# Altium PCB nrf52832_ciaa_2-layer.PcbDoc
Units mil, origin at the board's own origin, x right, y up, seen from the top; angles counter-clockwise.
Board outline 354 x 353 mil, 4 copper layers (Top Layer, Mid-Layer 1, Mid-Layer 2, Bottom Layer), stack 39.8 mil thick; 14 components, 27 nets, 89 pads, 13 vias.
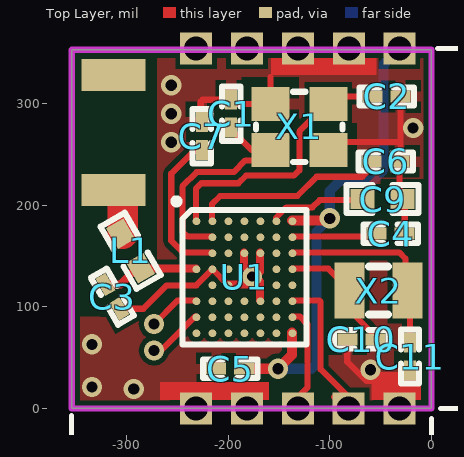
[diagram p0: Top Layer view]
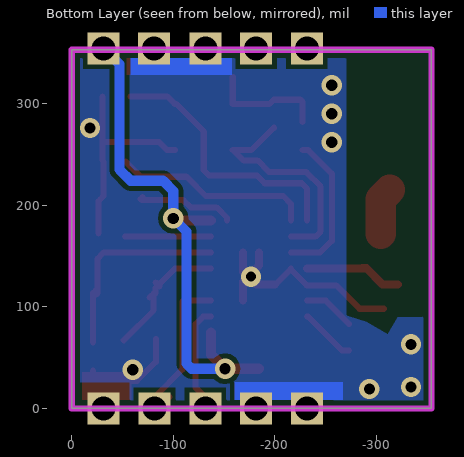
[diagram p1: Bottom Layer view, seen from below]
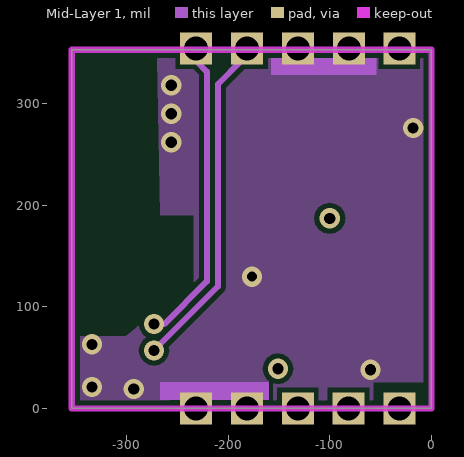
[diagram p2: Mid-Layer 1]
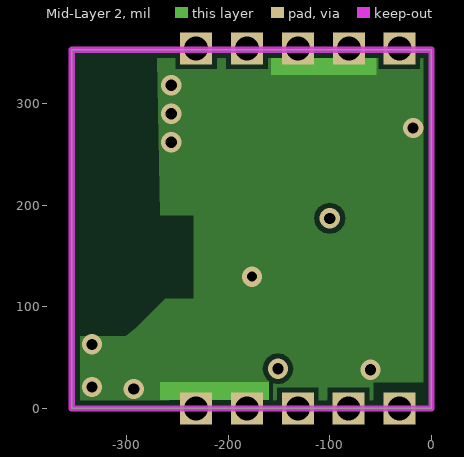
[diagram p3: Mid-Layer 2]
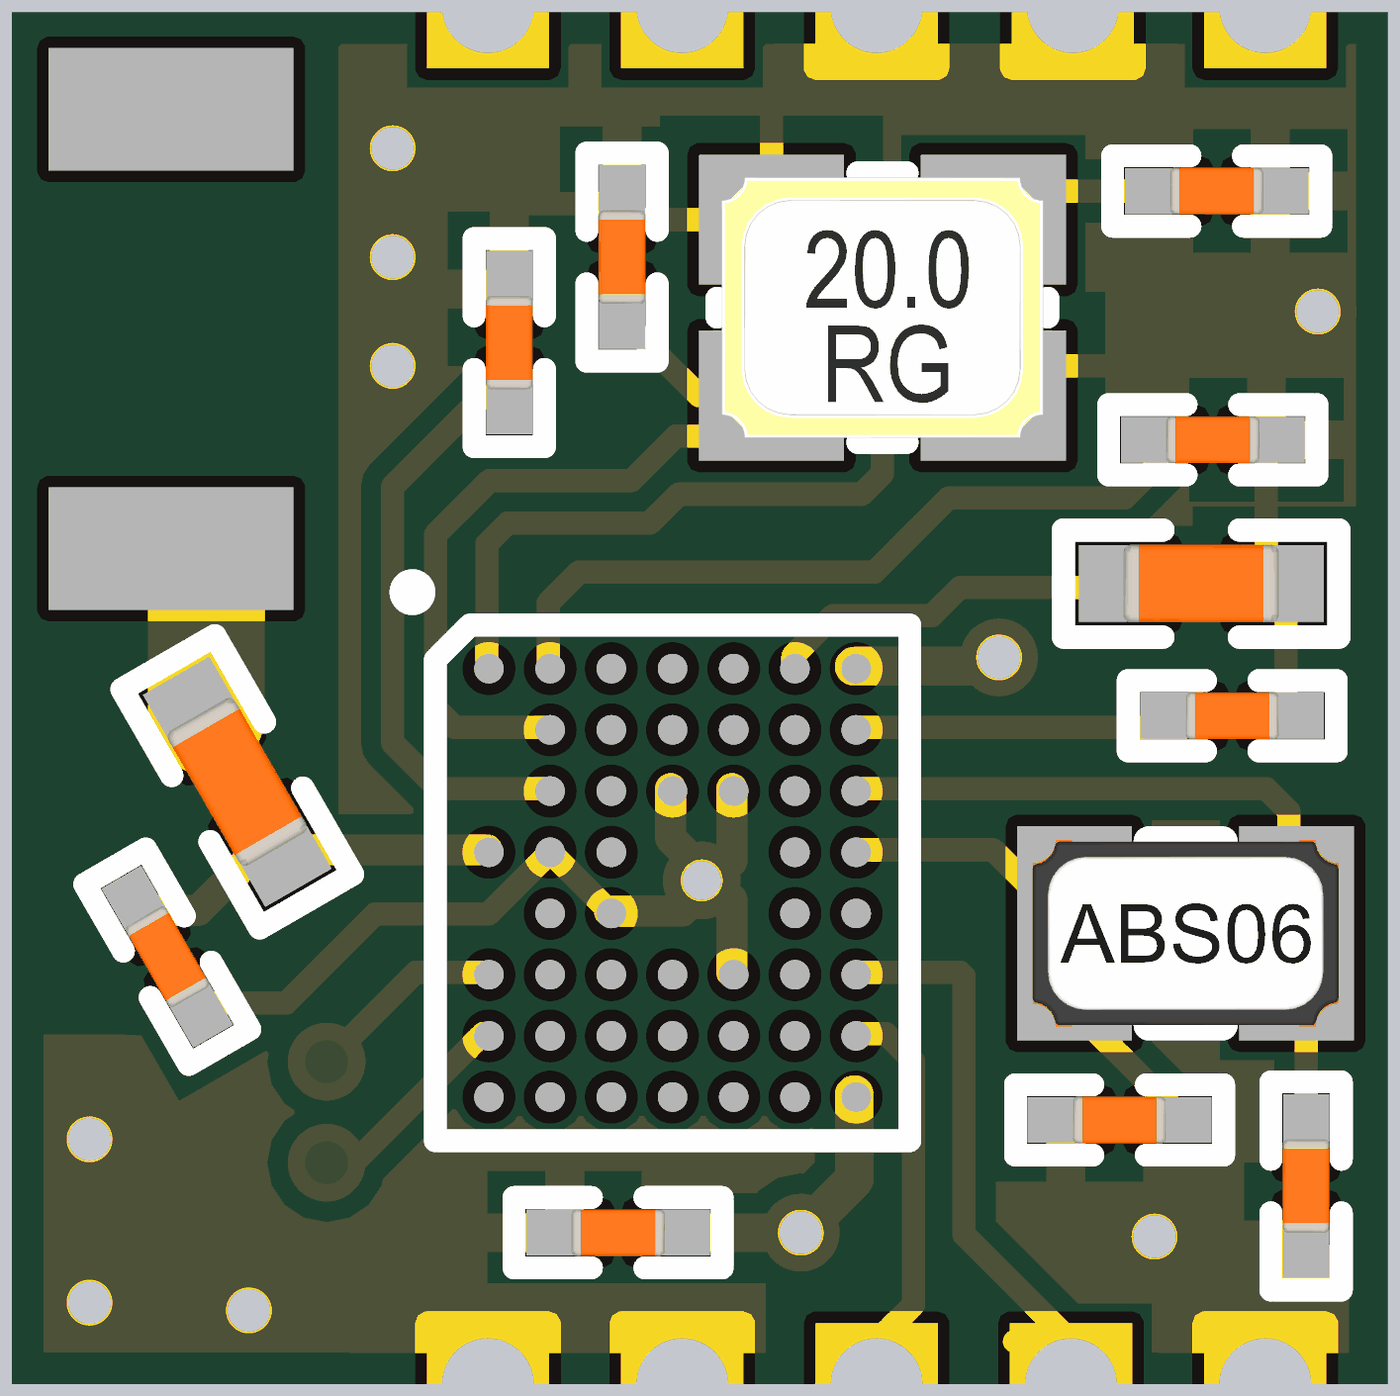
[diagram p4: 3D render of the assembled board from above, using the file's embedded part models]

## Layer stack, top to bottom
Top Layer: signal copper 1.4
Dielectric: core 9, FR-4, Dk 4.8
Mid-Layer 1: signal copper 1.4
Dielectric: prepreg 12.6, FR-4, Dk 4.8
Mid-Layer 2: signal copper 1.4
Dielectric: core 12.6, FR-4, Dk 4.8
Bottom Layer: signal copper 1.4

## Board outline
-354,0 0,0 0,353 -354,353

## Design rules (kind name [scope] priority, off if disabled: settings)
Clearance Polygon_ANT [(InNamedPolygon('Top_Layer-GND')) or (InNamedPolygon('Bottom_Layer-GND')) vs InNet('RF')] p1: gap=4
Clearance Polygon [(InNamedPolygon('Top_Layer-GND')) or (InNamedPolygon('Bottom_Layer-GND')) or (InNamedPolygon('Mid_Layer_1-GND')) or (InNamedPolygon('Mid_Layer_2-GND'))] p2: gap=8
Clearance [All] p3: gap=5
ComponentClearance [All] p1 off: gap=10 collisioncheckmode=3 verticalgap=10 showdistances=FALSE
FabricationTestPointUsage TestPointUsage [All] p1: valid=0 allowmultiple=FALSE
FabricationTestpoint Testpoint [All] p1: side=3 testpointundercomponent=TRUE minsize=40 maxsize=100 preferedsize=60 minholesize=0 maxholesize=40 preferedholesize=32 testpointgrid=1 allowsidetop=TRUE allowsidebottom=TRUE usegrid=TRUE gridtolerance=0.01
Height [All] p1 off: minheight=0 maxheight=1000 prefheight=500
HoleSize [All] p1: absolutevalues=TRUE maxlimit=160 minlimit=3 maxpercent=80.000 minpercent=20.000
HoleToHoleClearance [All] p1 off: gap=0 allowstackedmicrovias=FALSE
MinimumAnnularRing [All] p1 off: minimumring=3.94
MinimumSolderMaskSliver [All] p1: minsoldermaskwidth=0
PolygonConnect PolygonConnect_1 [isVia and innet(gnd)] p1: connectstyle=Direct reliefconductorwidth=10 reliefentries=4 polygonreliefangle="90 Angle" airgapwidth=10
PolygonConnect [All] p2: connectstyle=Relief reliefconductorwidth=10 reliefentries=4 polygonreliefangle="90 Angle" airgapwidth=10
RoomDefinition nrf52832_ciaa_2-layer [InComponentClass('nrf52832_ciaa_2-layer')] p1: confinementstyle=ConfineIn formatcopy=TRUE lockcomponents=FALSE outline -3405.3,-3455.81 -1405.3,-3455.81 -1405.3,-2455.81 -3405.3,-2455.81
RoutingVias [All] p1: holewidth=16 width=32 viastyle="Through Hole" minholewidth=3.94 minwidth=9.84 maxholewidth=28 maxwidth=50
SilkToSilkClearance [All] p1: silktosilkclearance=0
SilkToSolderMaskClearance SilkscreenOverComponentPads [IsPad] p1: minsilkscreentomaskgap=0 clearancetoexposedcopper=TRUE
SolderMaskExpansion [All] p1: expansion=3
Width [All] p1: maxlimit=100 minlimit=3 preferedwidth=6 toplayer_minwidth=5 bottomlayer_minwidth=5 minimp=50.000000 maximp=50.000000 favimp=50.000000
19 further rules are at their usual default settings.

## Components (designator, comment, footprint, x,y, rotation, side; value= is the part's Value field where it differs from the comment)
C1 "12pF" CAPC0603X03L -197,290 r270 top (schematic designator C8)
C2 "12pF" CAPC0603X03L -44,307 r180 top (schematic designator C8)
C3 "1.0pF" CAPC0603X03L -314,110 r120 top (schematic designator C8)
C4 "100nF" CAPC0603X03L -40,172 r0 top (schematic designator C8)
C5 "100nF" CAPC0603X03L -198,39 r180 top (schematic designator C8)
C6 "100pF" CAPC0603X03L -45,243 r180 top (schematic designator C8)
C7 "100pF" CAPC0603X03L -226,268 r90 top (schematic designator C8)
C9 "1.0µF" CAPC1005X04L -48,206 r180 top (schematic designator C8)
C10 "12pF" CAPC0603X03L -69,68 r0 top (schematic designator C8)
C11 "12pF" CAPC0603X03L -21,51 r90 top (schematic designator C8)
L1 "3.3nH" CAPC1005X04L -296,155 r120 top (schematic designator C8)
U1 "nRF52832-CIAA" BGA50C40P7X8_295X322X50 -184,129 r0 top
X1 "32MHz" BT-XTAL_2016 -130,277 r0 top
X2 "32.768kHz" XTAL_2012 -52,116 r0 top

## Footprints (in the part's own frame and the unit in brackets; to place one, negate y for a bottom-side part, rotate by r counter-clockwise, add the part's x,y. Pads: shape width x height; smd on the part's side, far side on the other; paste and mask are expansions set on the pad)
BGA50C40P7X8_295X322X50 [mm]
  round 0.193 smd: A1(-1.2,1.4) A2(-0.8,1.4) A3(-0.4,1.4) A4(0,1.4) A5(0.4,1.4) A6(0.8,1.4) A7(1.2,1.4) B2(-0.8,1) B3(-0.4,1) B4(0,1) B5(0.4,1) B6(0.8,1) B7(1.2,1) C2(-0.8,0.6) C3(-0.4,0.6) C4(0,0.6) C5(0.4,0.6) C6(0.8,0.6) C7(1.2,0.6) D1(-1.2,0.2) D2(-0.8,0.2) D3(-0.4,0.2) D6(0.8,0.2) D7(1.2,0.2) E2(-0.8,-0.2) E3(-0.4,-0.2) E6(0.8,-0.2) E7(1.2,-0.2) F1(-1.2,-0.6) F2(-0.8,-0.6) F3(-0.4,-0.6) F4(0,-0.6) F5(0.4,-0.6) F6(0.8,-0.6) F7(1.2,-0.6) G1(-1.2,-1) G2(-0.8,-1) G3(-0.4,-1) G4(0,-1) G5(0.4,-1) G6(0.8,-1) G7(1.2,-1) H1(-1.2,-1.4) H2(-0.8,-1.4) H3(-0.4,-1.4) H4(0,-1.4) H5(0.4,-1.4) H6(0.8,-1.4) H7(1.2,-1.4)
  silkscreen extent -1.75,-1.69 1.55,1.95, body extent -1.48,-1.61 1.48,1.61, height 0.51
BT-XTAL_2016 [mm] "Crystal 2.0 x 1.6 mm"
  rect 0.95x0.85 smd: 1(-0.725,-0.575) 2(0.725,-0.575) 3(0.725,0.575) 4(-0.725,0.575)
  silkscreen extent -1.08,-0.88 1.08,0.88, body extent -1.05,-0.85 1.05,0.85, height 0.56
CAPC0603X03L [mm]
  rect 0.5x0.3 smd: 1(-0.35,0) 2(0.35,0)
  silkscreen extent -0.68,-0.23 0.68,0.23, body extent -0.3,-0.15 0.31,0.15, height 0.3
CAPC1005X04L [mm] "Chip Capacitor, 2-Leads, Body 1.0x0.5mm, IPC High Density"
  rect 0.6x0.5 smd: 1(-0.5,0) 2(0.5,0)
  silkscreen extent -0.9,-0.35 0.9,0.35, body extent -0.51,-0.25 0.51,0.25, height 0.5
XTAL_2012 [mm] "XTAL SMD 2.0 x 1.2 mm"
  rect 0.75x1.4 smd: 1(-0.725,0) 2(0.725,0)
  silkscreen extent -0.24,-0.6 0.24,0.6, body extent -1,-0.61 1,0.61, height 0.6

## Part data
C1 C2 C10 C11: library part C0201-12p, "Capacitor, NP0, ±2%"
C3: library part C0201-1.0p, "Capacitor, NP0, ±5%"
C4 C5: library part C0201-100n, "Capacitor, X7R, ±10%"
C6 C7: library part C0201-100p, "Capacitor, NP0, ±5%"
C9: library part C0402-1μ0, "Capacitor, X5R, ±5%"
L1: library part L0201-3n3, "High frequency chip inductor ±5%"
U1: "Multi-protocol Bluetooth Low Energy, ANT and 2.4GHz proprietary system-on-chip"
X1: library part XTAL_SMD2016_32MHz_8pF_Epson, "XTAL SMD 2016, 32MHz, Cl=8pF, Total Tol: ±40ppm"
X2: library part XTAL_SMD2012_32.768kHz_9pF_Seiko, "XTAL SMD 2012, 32.768kHz, Cl=9pF, Total Tol: ±50ppm"

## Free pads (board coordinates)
  rect 62.99x31.5 smd: 0(-313,215) 0(-313,328)
  rect 31.5x31.5 hole 23.62: 1(-231.5,0) 2(-181.5,0) 3(-131.5,0) 4(-81.5,0) 5(-31.5,0) 6(-31.5,354.33) 7(-81,354.33) 8(-131.5,354.33) 9(-181.5,354.33) 10(-231.5,354.33)

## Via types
v1: diameter 20, hole 11, Top Layer to Bottom Layer, tented both sides, 10 vias
v2: diameter 20, hole 11, Top Layer to Mid-Layer 1, tented top, 2 vias
v3: diameter 20, hole 10, Top Layer to Bottom Layer, tented both sides, 1 vias

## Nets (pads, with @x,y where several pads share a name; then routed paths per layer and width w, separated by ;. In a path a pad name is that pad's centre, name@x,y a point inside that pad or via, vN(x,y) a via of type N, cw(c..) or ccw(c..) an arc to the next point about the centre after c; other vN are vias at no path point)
DEC1: C4.1 U1.B7 | length 84.9
  Top Layer w6: U1.B7@-137.25,168.99 C4.1@-52.4,168.99
DEC2: C6.2 U1.A2 | length 196.9
  Top Layer w6: U1.A2@-215.99,184.74 -215.99,201.01 -208,209 -132,209 -113,228 -67.78,228 C6.2@-52.78,243
DEC3: C7.1 U1.C2 | length 149.5
  Top Layer w6: C7.1@-227,254.22 -232.78,254.22 -256,231 -256,165 -244.24,153.24 U1.C2@-215.99,153.24
DEC4: C9.2 U1.A6 | length 98.5
  Top Layer w6: U1.A6@-153,184.74 -153,187.38 -142.64,197.74 -117.26,197.74 -110,205 -68.68,205 C9.2 C9.2@-69.68,208
GND: C1.1 C2.1 C3.1 C4.2 C5.2 C6.1 C7.2 C9.1 C10.1 C11.1 pad.1 pad.2 pad.5 pad.7 pad.8 U1.C4 U1.C5 U1.D2 U1.E3 U1.F5 X1.2 X1.4 | length 709.3
  Top Layer w6: C3.1 -283.39,98.07 -260.46,121 -231.37,121 U1.D2 ; C7.2@-227,281.78 -227,302 -225.22,303.78 -199,303.78 -194.86,299.64 X1.4 -158.54,326 ; U1.D2@-215.99,137.5 -215.43,136.94 U1.E3@-200.24,121.75 ; X1.2 -93.64,254.36 -86,262 -30.22,262 ; C10.1 -82.78,45.78 -64,27 -47.5,27 pad.5@-31.5,11 ; pad.5 -31.5,7.5 -21,18 C11.1 ; C6.1 -31.22,208.91 C9.1 -26.22,203.91 C4.2 ; C6.1@-30.22,244 -30.22,262 ; C2.1 -30.22,275 ; v1(-18,276) -29.22,276 -30.22,275 ; -30.22,262 -30.22,275
  Top Layer w8: U1.E3@-200.24,121.75 -181.5,121.75 v3@-173.62,129.62 ; U1.C4@-184.5,153.24 -184.5,140.5 v3@-173.62,129.62 ; U1.F5@-168.75,106 -168.75,124.75 v3@-173.62,129.62 ; U1.C5@-168.75,153.24 -168.75,134.5 v3@-173.62,129.62
  other v1: -293,19 -334,21 -60,38 -334,63 -256,262 -256,290 -256,318
  other v3: -176.5,129.62
NetC3_2: C3.2 L1.1 U1.D1 | length 96.6
  Top Layer w8: C3.2 -306.07,121.93 -290.05,137.95 L1.1 ; L1.1@-287,137.5 U1.D1@-231.74,137.5
P0.00/XL1: C10.2 U1.D7 X2.1 | length 137.1
  Top Layer w6: U1.D7@-137.25,137.5 -101.5,137.5 X2.1@-85.28,121.27 ; X2.1@-86.43,120.11 X2.1@-85.28,121.27 ; X2.1@-82.54,113 -82.54,118.54 X2.1@-85.28,121.27 ; X2.1@-82.54,124 X2.1@-85.28,121.27 ; X2.1@-76.78,109.24 -80.54,113 -80.54,96.32 C10.2@-51.22,67
P0.01/XL2: C11.2 U1.C7 X2.2 | length 202
  Top Layer w6: U1.C7@-137.25,153.24 -31.24,153.24 -25.46,147.46 X2.2@-25.46,113 ; X2.2@-24.22,112.24 X2.2@-23.46,113 ; X2.2 -21,113.54 C11.2
P0.05/AIN3: U1.E7
P0.06: pad.4 U1.F7 | length 148.6
  Top Layer w6: U1.F7@-137.25,106 -110,106 -109,105 -109,38.5 -81.5,11 pad.4@-96,11
P0.08: pad.3 U1.G7 | length 94.2
  Top Layer w6: U1.G7@-137.25,90.25 -129.25,90.25 -122,83 -122,67.37 -122,36.12 -122,20.5 pad.3@-131.5,11
P0.12: U1.H6
P0.14: U1.H5
P0.15: U1.H4
P0.16: U1.H3
P0.18: U1.H2
P0.21: U1.H1
P0.24: 
P0.28/AIN4: U1.A3
P0.29/AIN5: U1.A4
P0.30/AIN6: U1.A5
RF: L1.2 pad.0@-313,215 | length 46.9
  Top Layer w30: pad.0@-313,215 -303.94,205.94 L1.2@-303.94,171.89
SWDCLK: pad.10 U1.F1 | length 351.4
  Top Layer w6: v2(-273,83) -250,106 U1.F1@-231.74,106
  Mid-Layer 1 w6: v2(-273,83) -263,83 -221,125 -221,331.5 pad.10@-231.5,342
  Bottom Layer w6: pad.10@-231.5,344.5 pad.10
SWDIO: pad.9 U1.G1 | length 381.2
  Top Layer w6: v2(-273,57) -265.94,57 -232.69,90.25 U1.G1@-231.74,90.25
  Mid-Layer 1 w6: v2(-273,57) -210,120 -210,319 -187,342 pad.9@-181.5,342
VDD_NRF: C5.1 pad.6 U1.A7 U1.H7 | length 515.5
  Top Layer w10: C5.1 v1(-151,39) -137.25,52.75 U1.H7@-137.25,74.5 ; U1.A7@-137.25,184.74 -102.26,184.74 v1(-100,187)
  Bottom Layer w10: v1(-151,39) -118,39 -113,44 -113,174 v1(-100,187) -100,214 -90,224 -58,224 -47,235 -47,338.83 pad.6
XC1: C1.2 U1.B2 X1.1 | length 226.4
  Top Layer w6: U1.B2@-215.99,168.99 -239.99,168.99 -245,174 -245,218.56 -231,232.56 -194.44,232.56 -183,244 -168.91,244 X1.1 -177.14,254.36 C1.2@-199,276.22
XC2: C2.2 U1.A1 X1.3 | length 265.5
  Top Layer w6: U1.A1@-231.74,184.74 -231.74,216.26 -226.44,221.56 -189.89,221.56 -182.44,229 -135.32,229 -130,234.32 -130,272.57 -102.93,299.64 X1.3 -94.09,307 C2.2
pads on no net: U1.B3 U1.B4 U1.B5 U1.B6 U1.C3 U1.C6 U1.D3 U1.D6 U1.E2 U1.E6 U1.F2 U1.F3 U1.F4 U1.F6 U1.G2 U1.G3 U1.G4 U1.G5 U1.G6

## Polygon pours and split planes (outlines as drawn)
GND on Top Layer "Top Layer-No Net" (solid, remove dead copper, pour order 88): -354,352 -354,0 0,0 0,352 -1,353
GND on Mid-Layer 1 "Top Layer-No Net" (solid, remove dead copper, pour order 90): -354,353 -354,0 0,0 0,353
GND on Mid-Layer 2 "Top Layer-No Net" (solid, remove dead copper, pour order 92): -354,353 -354,0 0,0 0,353
GND on Bottom Layer "Top Layer-No Net" (solid, remove dead copper, pour order 98): -354,352 -354,1 -1,1 0,2 0,353

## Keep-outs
Keep-Out Layer:
  the board outline again, w6

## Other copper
Top Layer:
  rectangle net GND: -267,8 -160,26
  rectangle net GND: -158,328 -54,345
  rectangle net GND: -59,8 -10,36
  pour cut-out: -354,352 -353,353 -270,353 -270,92 -271,91 -304,89 -326,90 -354,90
Mid-Layer 1:
  rectangle net GND: -267,8 -160,26
  rectangle net GND: -158,328 -54,345
  pour cut-out: -354,352 -353,353 -270,353 -267,190 -234,190 -234,108 -262,108 -290,80 -301,71 -354,71
Mid-Layer 2:
  rectangle net GND: -267,8 -160,26
  rectangle net GND: -158,328 -54,345
  pour cut-out: -354,352 -353,353 -270,353 -267,190 -234,190 -234,108 -262,108 -290,80 -301,71 -354,71
Bottom Layer:
  rectangle net GND: -267,8 -160,26
  rectangle net GND: -158,328 -58,345
  pour cut-out: -354,352 -353,353 -270,353 -270,92 -271,91 -289.67,85.22 -310.96,72.93 -320.68,89.76 -354,90

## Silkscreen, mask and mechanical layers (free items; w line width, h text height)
Top Overlay:
  lines w5: -354.33,-140 -354.33,-7 ; 0,-143 0,-10 ; 6,354.33 139,354.33 ; 9,0 142,0
  lines w10: -454.33,-140 -354.33,-140 ; -414.33,-160 -354.33,-140 ; -414.33,-120 -354.33,-140 ; -354.33,-150 -354.33,-130 ; 0,-150 0,-130 ; 60,-160 0,-140 ; 60,-120 0,-140 ; 100,-140 0,-140 ; 119,-60 139,0 ; 119,414.33 139,354.33 ; 129,0 149,0 ; 129,354.33 149,354.33 ; 139,-100 139,0 ; 139,454.33 139,354.33 ; 159,-60 139,0 ; 159,414.33 139,354.33
  text "354.331 (mil)" at 282.96,-173.72 h60 r90
  text "354.331 (mil)" at -528.05,-283.96 h60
